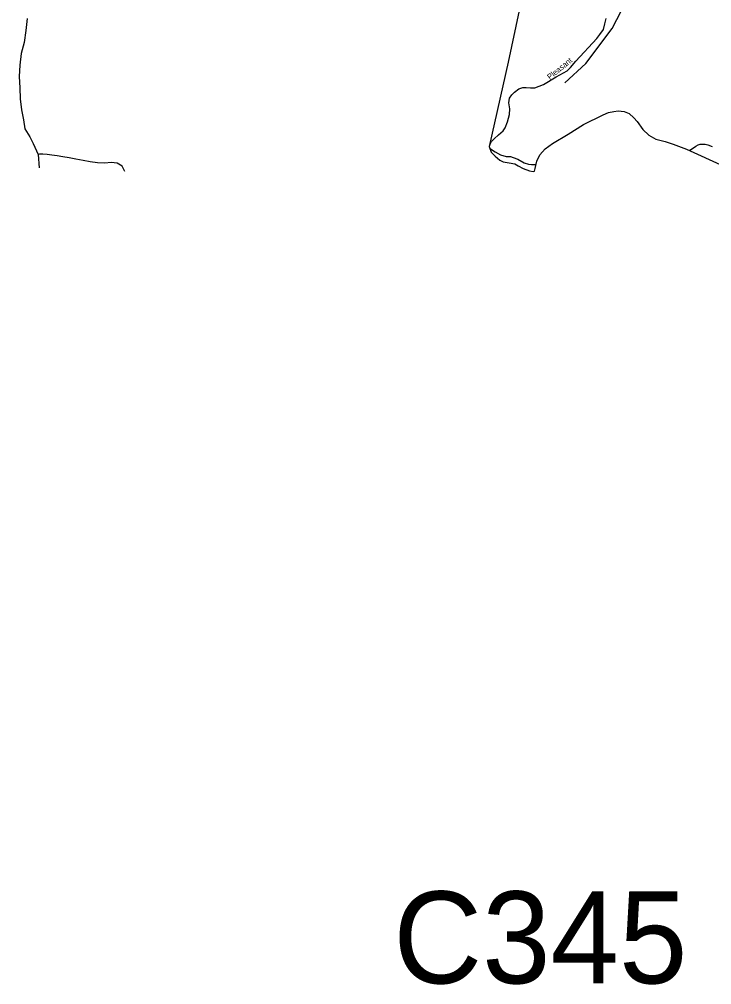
# Model space of a CAD drawing. Extents: x 884530 to 1028605, y 526725 to 653634.
# Drawn here: x 915314 to 923339, y 559581 to 570777 of the extents above; entities that cross this region are included whole.
import ezdxf

# ---------------------------------------------------------------- set-up
doc = ezdxf.new("R2010")
doc.units = 0
for name, color, linetype in [('Exist Boundary Political CountyLine', 7, 'Continuous'), ('Exist Hydrographic Creek Single Shore', 7, 'Continuous'), ('Exist Road Non-System Type 51', 7, 'Continuous'), ('Exist Road Secondary Structure Culvert Number Label', 7, 'Continuous'), ('Exist Road Secondary Type 51 Attributed', 7, 'Continuous'), ('Exist Road Secondary Type 51 Label', 7, 'Continuous')]:
    doc.layers.add(name, color=color, linetype=linetype)

msp = doc.modelspace()

# ---------------------------------------------------------------- linework, layer by layer
at = {"layer": 'Exist Boundary Political CountyLine'}
msp.add_lwpolyline([(922200, 576021), (920981, 570280), (920762, 569303), (920782, 569237), (920828, 569190), (920883, 569144), (920922, 569122), (920990, 569112), (921059, 569102), (921096, 569078), (921155, 569045), (921226, 569020), (921270, 569013), (921286, 569015), (921293, 569046), (921311, 569131), (921347, 569203), (921410, 569273), (921496, 569336), (921674, 569444), (921852, 569556), (922080, 569669), (922145, 569695), (922206, 569709), (922256, 569715), (922324, 569706), (922383, 569686), (922437, 569634), (922476, 569591), (922540, 569498), (922612, 569432), (922691, 569387), (922800, 569359), (922893, 569328), (922954, 569307), (923047, 569272), (924303, 568698)], dxfattribs=at)
at = {"layer": 'Exist Hydrographic Creek Single Shore'}
msp.add_lwpolyline([(921639, 570038), (921881, 570263), (922187, 570671), (922348, 570982)], dxfattribs=at)
at = {"layer": 'Exist Road Non-System Type 51'}
msp.add_line((915534, 569210), (915543, 569053), dxfattribs=at)
for points in [[(915406, 570786), (915390, 570648), (915370, 570509), (915337, 570379), (915320, 570243), (915314, 570114), (915319, 569983), (915326, 569853), (915338, 569727), (915361, 569609), (915379, 569507), (915436, 569413), (915474, 569337), (915534, 569210)], [(916538, 569013), (916506, 569072), (916449, 569109), (916379, 569115), (916305, 569110), (916222, 569113), (916137, 569125), (916053, 569141), (915971, 569156), (915893, 569170), (915820, 569183), (915752, 569193), (915691, 569202), (915636, 569209), (915587, 569212), (915549, 569212), (915534, 569210)], [(920774, 569276), (920828, 569240), (920890, 569203), (920957, 569185), (921006, 569185), (921039, 569175), (921093, 569153), (921165, 569113), (921217, 569098), (921252, 569093), (921302, 569091)]]:
    msp.add_lwpolyline(points, dxfattribs=at)
at = {"layer": 'Exist Road Secondary Type 51 Attributed'}
for points in [[(920770, 569276), (920766, 569288), (920765, 569298), (920765, 569304), (920772, 569327), (920789, 569358), (920817, 569389), (920867, 569435), (920921, 569483), (920944, 569519), (920974, 569586), (920996, 569673), (920998, 569738), (920988, 569809), (920996, 569862), (921021, 569900), (921054, 569932), (921105, 569969), (921150, 569986), (921188, 569987), (921240, 569981), (921290, 569982), (921340, 570002), (921389, 570020), (921538, 570111), (921665, 570178), (921703, 570218), (921763, 570293), (922009, 570553), (922043, 570602), (922087, 570659), (922100, 570725), (922117, 570785)], [(923083, 569256), (923156, 569307), (923183, 569322), (923205, 569327), (923236, 569329), (923263, 569328), (923296, 569321), (923345, 569300)]]:
    msp.add_lwpolyline(points, dxfattribs=at)

# ---------------------------------------------------------------- texts
at = {"layer": 'Exist Road Secondary Structure Culvert Number Label'}
msp.add_text('C345', height=1066.3, dxfattribs=at).set_placement((919649, 559596))
at = {"layer": 'Exist Road Secondary Type 51 Label'}
msp.add_text('Pleasant', height=65.6, rotation=38.8243, dxfattribs=at).set_placement((921464, 570073))

doc.saveas('drawing.dxf')
